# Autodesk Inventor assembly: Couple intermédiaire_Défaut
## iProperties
Shininess: 64.0
Length Units: 11269
Angle Units: 11279
Time Units: 11290
Mass Units: 11283
Length Display Precision: 3
Angle Display Precision: 2
Compacted: True
Created: 2006-01
Part Number: Couple intermédiaire_Défaut
Document SubType Name: Assembly
Designer: riri
Density: 0.0
Volumn: 0.0
Area: 0.0
PropertySet Name: Model Information
Control State: 0
Master: False
Checked Out: False
Author: riri
